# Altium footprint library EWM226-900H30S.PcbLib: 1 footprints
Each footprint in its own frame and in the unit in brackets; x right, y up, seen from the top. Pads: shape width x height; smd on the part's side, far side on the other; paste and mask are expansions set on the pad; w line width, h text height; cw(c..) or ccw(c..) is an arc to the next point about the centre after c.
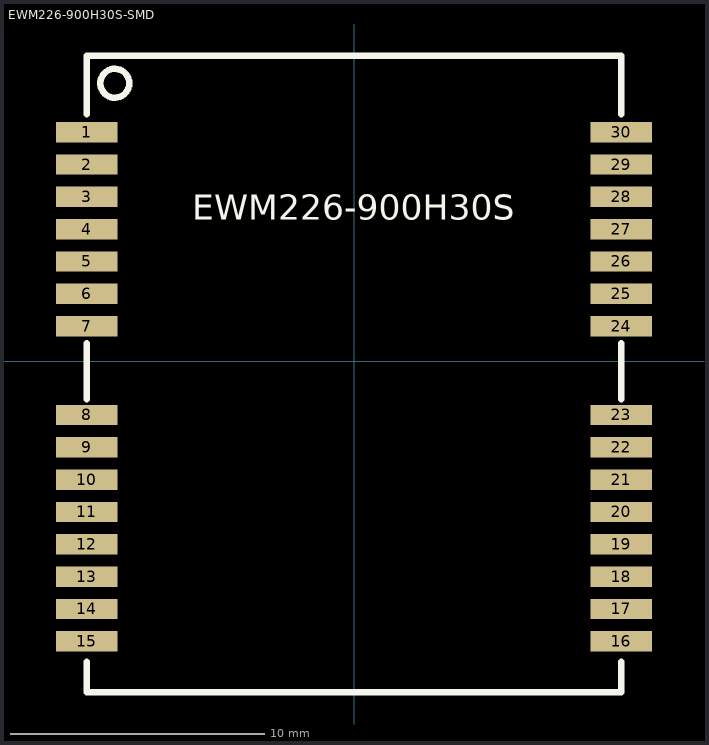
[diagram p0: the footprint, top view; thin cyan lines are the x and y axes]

## EWM226-900H30S-SMD [mm]
pads (30):
  rect 2.4x0.8 smd paste-2.4 mask-2.4: 1(-10.5,9) 2(-10.5,7.73) 3(-10.5,6.46) 4(-10.5,5.19) 5(-10.5,3.92) 6(-10.5,2.65) 7(-10.5,1.38) 8(-10.5,-2.11) 9(-10.5,-3.38) 10(-10.5,-4.65) 11(-10.5,-5.92) 12(-10.5,-7.19) 13(-10.5,-8.46) 14(-10.5,-9.73) 15(-10.5,-11) 16(10.5,-11) 17(10.5,-9.73) 18(10.5,-8.46) 19(10.5,-7.19) 20(10.5,-5.92) 21(10.5,-4.65) 22(10.5,-3.38) 23(10.5,-2.11) 24(10.5,1.38) 25(10.5,2.65) 26(10.5,3.92) 27(10.5,5.19) 28(10.5,6.46) 29(10.5,7.73) 30(10.5,9)
Top Overlay:
  circle w0.254: c-9.398,10.922 r0.568
  lines w0.254: -10.5,-11.8 -10.5,-13 10.5,-13 10.5,-11.8 ; -10.5,-1.5 -10.5,0.7 ; -10.5,9.7 -10.5,12 10.5,12 10.5,9.7 ; 10.5,-1.5 10.5,0.7
  text "EWM226-900H30S" at -6.35,5.225 h1.7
